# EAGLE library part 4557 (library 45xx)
1 to 64 bit variable length SHIFT REGISTER
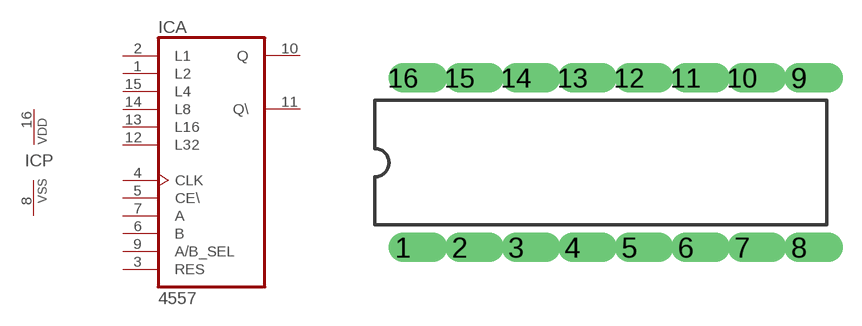
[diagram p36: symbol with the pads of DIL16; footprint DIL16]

Designator prefix IC; gates A=4557 P=PWRN

## 4557N  [DIL16]
1  A:L2  in
2  A:L1  in
3  A:RES  in
4  A:CLK  in
5  A:CE\  in
6  A:B  in
7  A:A  in
8  P:VSS  pwr
9  A:A/B_SEL  in
10  A:Q  out
11  A:Q\  out
12  A:L32  in
13  A:L16  in
14  A:L8  in
15  A:L4  in
16  P:VDD  pwr

## Footprint DIL16 (pad centres in mm)
Dual In Line
drill 0.813 offset: 1 -8.89,-3.81; 2 -6.35,-3.81; 3 -3.81,-3.81; 4 -1.27,-3.81; 5 1.27,-3.81; 6 3.81,-3.81; 7 6.35,-3.81; 8 8.89,-3.81; 9 8.89,3.81; 10 6.35,3.81; 11 3.81,3.81; 12 1.27,3.81; 13 -1.27,3.81; 14 -3.81,3.81; 15 -6.35,3.81; 16 -8.89,3.81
